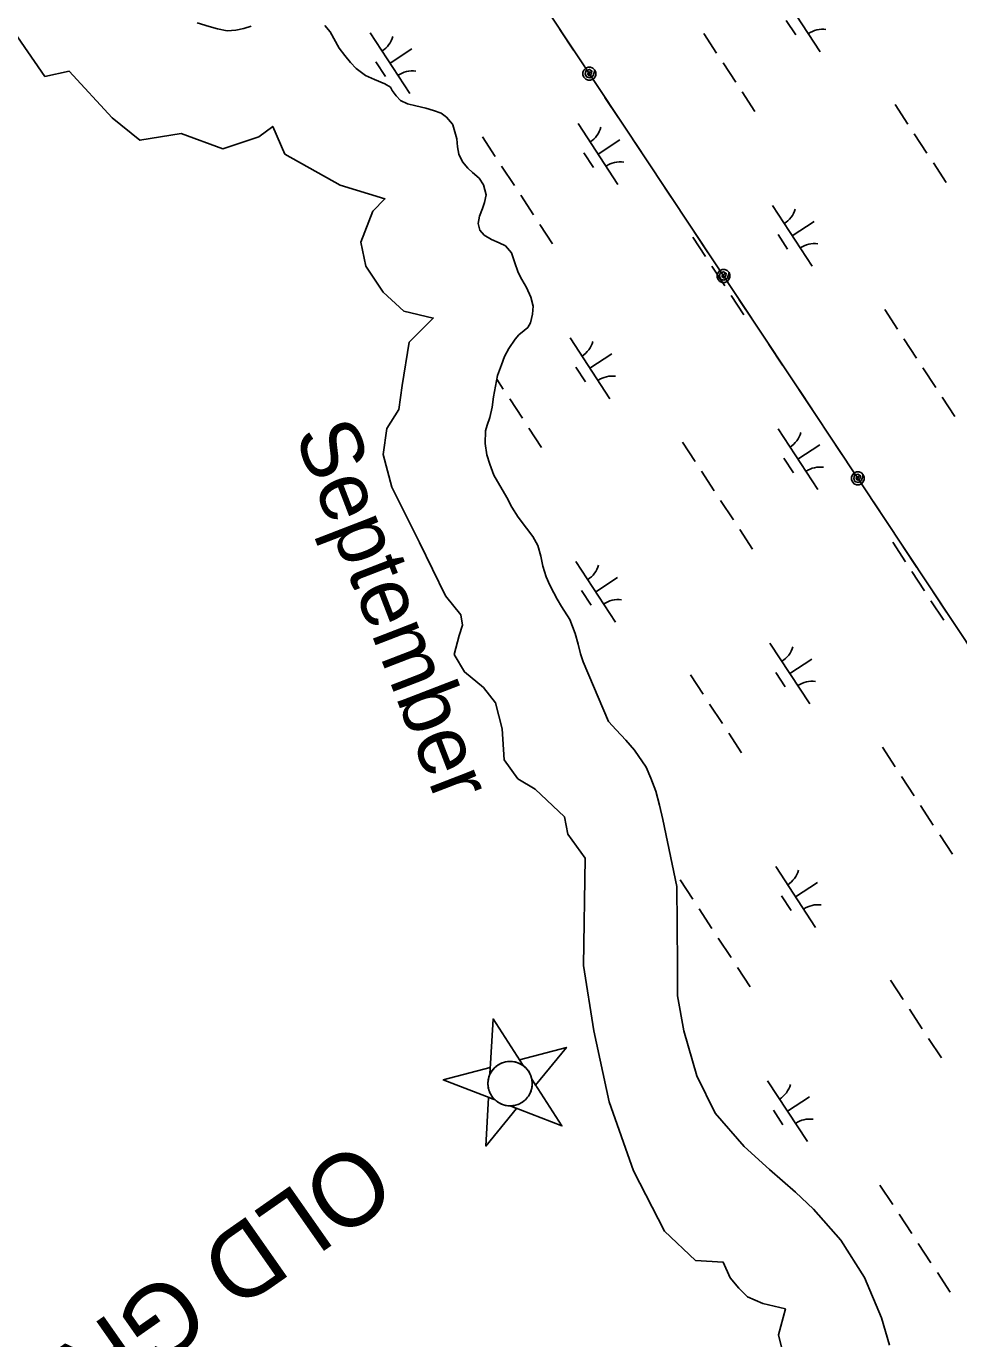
# Model space of a CAD drawing. Extents: x 3945642 to 3966284, y 206476 to 228921.
# Drawn here: x 3958060 to 3958701, y 215442 to 216345 of the extents above; entities that cross this region are included whole.
import ezdxf

# ---------------------------------------------------------------- set-up
doc = ezdxf.new("R2010")
doc.units = 0
for name, color, linetype in [('V-CHAN-NAID', 7, 'Continuous'), ('V-RIVR-EDGE', 7, 'Continuous'), ('V-RIVR-IDEN', 7, 'Continuous'), ('V-UTIL-LINE', 7, 'Continuous'), ('V-WETL-SWMP', 7, 'Continuous')]:
    doc.layers.add(name, color=color, linetype=linetype)

msp = doc.modelspace()

# ---------------------------------------------------------------- linework, layer by layer
at = {"layer": 'V-CHAN-NAID'}
for points in [[(3958401.45, 215629.91), (3958380.76, 215662.08), (3958378.6, 215623.89), (3958379.09, 215624.88), (3958379.55, 215625.66), (3958380.15, 215626.55), (3958380.82, 215627.4), (3958381.27, 215627.91), (3958381.86, 215628.51), (3958382.39, 215629.01), (3958383.01, 215629.52), (3958383.71, 215630.04), (3958384.37, 215630.48), (3958385.26, 215631), (3958385.99, 215631.37), (3958387.02, 215631.81), (3958387.96, 215632.13), (3958388.91, 215632.4), (3958389.79, 215632.58), (3958390.66, 215632.71), (3958391.52, 215632.79), (3958392.54, 215632.82), (3958393.44, 215632.79), (3958394.24, 215632.72), (3958394.99, 215632.62), (3958395.91, 215632.43), (3958396.6, 215632.26), (3958397.66, 215631.92), (3958398.35, 215631.65), (3958399.26, 215631.24), (3958400.13, 215630.77), (3958400.81, 215630.35)], [(3958401.45, 215629.91), (3958398.86, 215633.94), (3958431.21, 215642.47), (3958410.05, 215616.56), (3958407.46, 215620.59), (3958407.27, 215621.41), (3958406.95, 215622.45), (3958406.58, 215623.43), (3958406.15, 215624.37), (3958405.88, 215624.89), (3958405.5, 215625.55), (3958405.03, 215626.27), (3958404.62, 215626.83), (3958404.02, 215627.57), (3958403.55, 215628.08), (3958402.9, 215628.72), (3958402.31, 215629.25), (3958401.89, 215629.59)], [(3958382.17, 215606.3), (3958346.52, 215620.15), (3958378.87, 215628.68), (3958378.6, 215623.89), (3958378.37, 215623.36), (3958377.97, 215622.27), (3958377.71, 215621.38), (3958377.48, 215620.35), (3958377.34, 215619.43), (3958377.25, 215618.51), (3958377.22, 215617.65), (3958377.25, 215616.66), (3958377.33, 215615.7), (3958377.48, 215614.72), (3958377.65, 215613.97), (3958377.87, 215613.14), (3958378.24, 215612.06), (3958378.54, 215611.34), (3958378.99, 215610.42), (3958379.37, 215609.75), (3958379.87, 215608.96), (3958380.36, 215608.28), (3958380.9, 215607.61), (3958381.55, 215606.9)], [(3958407.46, 215620.59), (3958428.15, 215588.43), (3958392.5, 215602.28), (3958393.37, 215602.31), (3958394.42, 215602.4), (3958395.27, 215602.54), (3958396.29, 215602.76), (3958397.19, 215603.02), (3958397.99, 215603.3), (3958398.93, 215603.7), (3958399.63, 215604.06), (3958400.59, 215604.61), (3958401.45, 215605.18), (3958402.32, 215605.87), (3958402.99, 215606.46), (3958403.79, 215607.28), (3958404.51, 215608.13), (3958405.13, 215608.99), (3958405.56, 215609.65), (3958406.09, 215610.6), (3958406.52, 215611.51), (3958406.9, 215612.49), (3958407.2, 215613.44), (3958407.42, 215614.34), (3958407.61, 215615.45), (3958407.73, 215616.56), (3958407.76, 215617.59), (3958407.72, 215618.69), (3958407.63, 215619.51)], [(3958392.5, 215602.28), (3958396.97, 215600.54), (3958375.81, 215574.64), (3958377.7, 215608.03), (3958382.17, 215606.3), (3958382.82, 215605.73), (3958383.5, 215605.21), (3958384.47, 215604.56), (3958385.32, 215604.07), (3958386.29, 215603.6), (3958387.28, 215603.2), (3958388.22, 215602.89), (3958389.06, 215602.67), (3958390.04, 215602.48), (3958390.95, 215602.36), (3958391.87, 215602.29)]]:
    msp.add_lwpolyline(points, close=True, dxfattribs=at)
msp.add_circle((3958392.49, 215617.55), 15.27, dxfattribs=at)
at = {"layer": 'V-RIVR-EDGE'}
msp.add_lwpolyline([(3958053.53, 216337.62), (3958072.53, 216310.31), (3958089.15, 216313.88), (3958118.83, 216281.82), (3958137.82, 216266.39), (3958166.32, 216271.14), (3958194.81, 216260.45), (3958219.74, 216268.76), (3958229.24, 216275.89), (3958237.55, 216256.89), (3958275.54, 216235.52), (3958306.41, 216226.02), (3958298.1, 216217.71), (3958289.79, 216196.34), (3958293.35, 216179.72), (3958305.22, 216161.91), (3958319.47, 216148.85), (3958339.65, 216144.11), (3958323.03, 216127.48), (3958318.28, 216097.8), (3958315.9, 216081.18), (3958307.59, 216068.12), (3958305.22, 216050.32), (3958311.16, 216027.76), (3958330.15, 215989.77), (3958347.96, 215952.96), (3958358.64, 215939.9), (3958359.83, 215932.78), (3958357.46, 215925.66), (3958353.9, 215912.6), (3958361.02, 215900.73), (3958374.08, 215890.04), (3958382.39, 215879.36), (3958387.14, 215861.55), (3958388.32, 215840.18), (3958397.82, 215827.12), (3958409.69, 215820), (3958429.88, 215801), (3958432.25, 215789.13), (3958444.12, 215772.51), (3958442.94, 215698.9), (3958450.06, 215653.79), (3958460.74, 215605.11), (3958477.37, 215557.62), (3958498.74, 215516.07), (3958520.1, 215495.89), (3958539.1, 215494.7), (3958543.85, 215484.01), (3958549.79, 215476.89), (3958555.72, 215470.96), (3958566.41, 215466.21), (3958581.84, 215462.65), (3958577.09, 215444.84), (3958579.47, 215435.34)], dxfattribs=at)
at = {"layer": 'V-UTIL-LINE'}
for points in [[(3958881.28, 222827.27), (3957109.88, 218326.97), (3961480.16, 211741.64)], [(3958426.79, 216342.56), (3958436.19, 216328.39)], [(3958446.98, 216312.17), (3958447.51, 216313.51), (3958446.38, 216313.24), (3958445.9, 216311.96), (3958446.84, 216310.83), (3958448.3, 216311.7), (3958448.82, 216313.99), (3958447.01, 216315.11), (3958444.7, 216314.36), (3958444.13, 216312.14), (3958444.93, 216310.05), (3958447.24, 216309.35), (3958449.62, 216310.74), (3958450.73, 216314.66), (3958449.49, 216315.91), (3958447.87, 216316.58), (3958446.11, 216316.59), (3958444.49, 216315.92), (3958443.24, 216314.69), (3958442.57, 216313.07), (3958442.56, 216311.31), (3958443.23, 216309.69), (3958444.47, 216308.44), (3958446.09, 216307.76), (3958447.84, 216307.76), (3958449.47, 216308.42), (3958450.71, 216309.66), (3958451.39, 216311.28), (3958451.39, 216313.04), (3958450.73, 216314.66)], [(3958457.76, 216295.9), (3958467.16, 216281.73)], [(3958478.22, 216265.07), (3958487.62, 216250.91)], [(3958498.68, 216234.24), (3958508.08, 216220.08)], [(3958519.13, 216203.41), (3958528.53, 216189.25)], [(3958539.32, 216173.03), (3958539.85, 216174.36), (3958538.72, 216174.1), (3958538.24, 216172.81), (3958539.18, 216171.69), (3958540.64, 216172.56), (3958541.16, 216174.84), (3958539.35, 216175.97), (3958537.04, 216175.21), (3958536.47, 216172.99), (3958537.28, 216170.91), (3958539.58, 216170.21), (3958541.96, 216171.59), (3958543.07, 216175.52), (3958541.83, 216176.76), (3958540.21, 216177.44), (3958538.46, 216177.44), (3958536.83, 216176.78), (3958535.59, 216175.54), (3958534.91, 216173.92), (3958534.9, 216172.16), (3958535.57, 216170.54), (3958536.81, 216169.29), (3958538.43, 216168.62), (3958540.18, 216168.61), (3958541.81, 216169.28), (3958543.05, 216170.52), (3958543.73, 216172.14), (3958543.74, 216173.89), (3958543.07, 216175.52)], [(3958550.1, 216156.75), (3958559.5, 216142.59)], [(3958570.56, 216125.92), (3958579.96, 216111.76)], [(3958591.02, 216095.09), (3958600.42, 216080.93)], [(3958611.48, 216064.27), (3958620.88, 216050.1)], [(3958631.66, 216033.88), (3958632.2, 216035.22), (3958631.06, 216034.95), (3958630.59, 216033.66), (3958631.53, 216032.54), (3958632.99, 216033.41), (3958633.51, 216035.7), (3958631.69, 216036.82), (3958629.38, 216036.06), (3958628.82, 216033.85), (3958629.62, 216031.76), (3958631.93, 216031.06), (3958634.31, 216032.44), (3958635.41, 216036.37), (3958634.18, 216037.61), (3958632.55, 216038.29), (3958630.8, 216038.3), (3958629.17, 216037.63), (3958627.93, 216036.39), (3958627.25, 216034.77), (3958627.25, 216033.02), (3958627.91, 216031.39), (3958629.15, 216030.15), (3958630.77, 216029.47), (3958632.53, 216029.46), (3958634.15, 216030.13), (3958635.4, 216031.37), (3958636.07, 216032.99), (3958636.08, 216034.75), (3958635.41, 216036.37)], [(3958642.44, 216017.61), (3958651.84, 216003.44)], [(3958662.9, 215986.78), (3958672.3, 215972.61)], [(3958683.36, 215955.95), (3958692.76, 215941.78)]]:
    msp.add_lwpolyline(points, dxfattribs=at)
at = {"layer": 'V-WETL-SWMP'}
for p, q in [((3958578.43, 216369), (3958605.83, 216327.18)), ((3958177.24, 216347.25), (3958185.58, 216344.59)), ((3958185.58, 216344.59), (3958191.12, 216342.97)), ((3958209.35, 216343.34), (3958214.33, 216344.82)), ((3958265.07, 216345.4), (3958268.79, 216340.9)), ((3958582.39, 216348.88), (3958588.97, 216338.84)), ((3958191.12, 216342.97), (3958197.88, 216341.62)), ((3958197.88, 216341.62), (3958203.79, 216342.08)), ((3958203.79, 216342.08), (3958209.35, 216343.34)), ((3958268.79, 216340.9), (3958274.83, 216329.83)), ((3958296.22, 216340.39), (3958323.62, 216298.57)), ((3958525.79, 216339.8), (3958534.56, 216326.42)), ((3958274.83, 216329.83), (3958278.9, 216324.76)), ((3958309.92, 216319.48), (3958324.98, 216329.34)), ((3958278.9, 216324.76), (3958282.76, 216319.83)), ((3958282.76, 216319.83), (3958286.62, 216315.84)), ((3958300.18, 216320.27), (3958306.75, 216310.23)), ((3958538.94, 216319.73), (3958547.71, 216306.34)), ((3958286.62, 216315.84), (3958292.93, 216310.9)), ((3958292.93, 216310.9), (3958299.32, 216308.11)), ((3958299.32, 216308.11), (3958306.29, 216305.32)), ((3958306.29, 216305.32), (3958310.17, 216302.99)), ((3958310.17, 216302.99), (3958311.45, 216300.68)), ((3958311.45, 216300.68), (3958314.02, 216297.05)), ((3958552.09, 216299.65), (3958560.86, 216286.27)), ((3958314.02, 216297.05), (3958317.16, 216293.72)), ((3958317.16, 216293.72), (3958321.9, 216291.38)), ((3958321.9, 216291.38), (3958327.66, 216290.04)), ((3958327.66, 216290.04), (3958334.42, 216288.41)), ((3958657.33, 216290.94), (3958666.09, 216277.55)), ((3958334.42, 216288.41), (3958339.81, 216286.93)), ((3958339.81, 216286.93), (3958344.99, 216284.94)), ((3958344.99, 216284.94), (3958348.65, 216282.25)), ((3958348.65, 216282.25), (3958352.79, 216277.54)), ((3958352.79, 216277.54), (3958353.08, 216277.1)), ((3958353.08, 216277.1), (3958355.75, 216267.28)), ((3958439.29, 216277.85), (3958466.69, 216236.03)), ((3958355.75, 216267.28), (3958356.36, 216261.95)), ((3958373.5, 216268.73), (3958382.27, 216255.34)), ((3958452.99, 216256.94), (3958468.05, 216266.8)), ((3958670.48, 216270.86), (3958679.25, 216257.48)), ((3958356.36, 216261.95), (3958357.33, 216256.82)), ((3958357.33, 216256.82), (3958359.81, 216251.55)), ((3958443.25, 216257.73), (3958449.83, 216247.69)), ((3958359.81, 216251.55), (3958363.31, 216247.2)), ((3958363.31, 216247.2), (3958366.61, 216244.29)), ((3958366.61, 216244.29), (3958371.12, 216240.3)), ((3958386.65, 216248.65), (3958395.42, 216235.27)), ((3958683.63, 216250.79), (3958692.4, 216237.4)), ((3958371.12, 216240.3), (3958374.19, 216235.73)), ((3958374.19, 216235.73), (3958375.94, 216228.95)), ((3958375.94, 216228.95), (3958374.96, 216223.62)), ((3958399.8, 216228.57), (3958408.57, 216215.19)), ((3958373.49, 216219.38), (3958371.37, 216214.28)), ((3958374.96, 216223.62), (3958373.49, 216219.38)), ((3958572.88, 216221.62), (3958600.28, 216179.8)), ((3958371.37, 216214.28), (3958370.46, 216209.24)), ((3958370.46, 216209.24), (3958371.73, 216204.55)), ((3958412.96, 216208.5), (3958421.72, 216195.12)), ((3958586.58, 216200.71), (3958601.64, 216210.58)), ((3958371.73, 216204.55), (3958374.66, 216201.07)), ((3958374.66, 216201.07), (3958379.61, 216198.22)), ((3958518.19, 216199.79), (3958526.95, 216186.4)), ((3958576.84, 216201.5), (3958583.41, 216191.47)), ((3958379.61, 216198.22), (3958384.93, 216195.95)), ((3958384.93, 216195.95), (3958389.38, 216193.83)), ((3958389.38, 216193.83), (3958393.52, 216188.9)), ((3958393.52, 216188.9), (3958395.57, 216182.83)), ((3958395.57, 216182.83), (3958398.04, 216175.54)), ((3958398.04, 216175.54), (3958400.67, 216170.69)), ((3958531.34, 216179.71), (3958540.11, 216166.33)), ((3958400.67, 216170.69), (3958403.8, 216165.05)), ((3958403.8, 216165.05), (3958406.71, 216158.47)), ((3958406.71, 216158.47), (3958408.4, 216152.33)), ((3958544.49, 216159.64), (3958553.26, 216146.25)), ((3958408, 216146.78), (3958406.44, 216140.74)), ((3958408.4, 216152.33), (3958408, 216146.78)), ((3958650.16, 216149.96), (3958658.93, 216136.57)), ((3958404.62, 216137.73), (3958402.23, 216135.65)), ((3958406.44, 216140.74), (3958404.62, 216137.73)), ((3958396.06, 216129.65), (3958391.69, 216123.19)), ((3958398.6, 216132.51), (3958396.06, 216129.65)), ((3958402.23, 216135.65), (3958398.6, 216132.51)), ((3958433.74, 216130.47), (3958461.14, 216088.65)), ((3958663.31, 216129.88), (3958672.08, 216116.5)), ((3958391.69, 216123.19), (3958388.69, 216117.66)), ((3958447.44, 216109.56), (3958462.5, 216119.42)), ((3958386.49, 216111.91), (3958383.77, 216104.66)), ((3958388.69, 216117.66), (3958386.49, 216111.91)), ((3958437.7, 216110.35), (3958444.27, 216100.31)), ((3958676.46, 216109.81), (3958685.23, 216096.42)), ((3958383.77, 216104.66), (3958381, 216089.83)), ((3958383.3, 216102.14), (3958387.82, 216095.25)), ((3958380.09, 216082.77), (3958378.45, 216075.8)), ((3958381, 216089.83), (3958380.09, 216082.77)), ((3958392.2, 216088.56), (3958400.97, 216075.18)), ((3958689.61, 216089.73), (3958698.38, 216076.35)), ((3958378.45, 216075.8), (3958376.76, 216070.4)), ((3958375.65, 216066.45), (3958375.23, 216057.73)), ((3958376.76, 216070.4), (3958375.65, 216066.45)), ((3958405.35, 216068.48), (3958414.12, 216055.1)), ((3958576.81, 216067.93), (3958604.21, 216026.11)), ((3958375.23, 216057.73), (3958376.54, 216050.01)), ((3958511.02, 216058.81), (3958519.79, 216045.42)), ((3958590.51, 216047.02), (3958605.57, 216056.88)), ((3958376.54, 216050.01), (3958378.51, 216043.73)), ((3958580.77, 216047.81), (3958587.35, 216037.77)), ((3958378.51, 216043.73), (3958381.41, 216036.07)), ((3958524.17, 216038.73), (3958532.94, 216025.35)), ((3958381.41, 216036.07), (3958390.31, 216020.58)), ((3958390.31, 216020.58), (3958393.79, 216014.07)), ((3958537.32, 216018.66), (3958546.09, 216005.27)), ((3958393.79, 216014.07), (3958397.93, 216007.2)), ((3958397.93, 216007.2), (3958403.78, 215999.52)), ((3958403.78, 215999.52), (3958408.21, 215993.86)), ((3958408.21, 215993.86), (3958411.48, 215987.57)), ((3958550.48, 215998.58), (3958559.24, 215985.2)), ((3958411.48, 215987.57), (3958413.59, 215980.35)), ((3958655.71, 215989.87), (3958664.48, 215976.48)), ((3958413.59, 215980.35), (3958415.05, 215973.42)), ((3958415.05, 215973.42), (3958417.38, 215966.06)), ((3958437.68, 215976.78), (3958465.07, 215934.96)), ((3958417.38, 215966.06), (3958419.93, 215960.42)), ((3958451.38, 215955.87), (3958466.43, 215965.73)), ((3958668.86, 215969.79), (3958677.63, 215956.41)), ((3958419.93, 215960.42), (3958422.56, 215955.07)), ((3958441.63, 215956.66), (3958448.21, 215946.62)), ((3958422.56, 215955.07), (3958424.83, 215950.65)), ((3958424.83, 215950.65), (3958427.9, 215945.66)), ((3958682.01, 215949.72), (3958690.78, 215936.33)), ((3958427.9, 215945.66), (3958433.63, 215936.69)), ((3958433.63, 215936.69), (3958437.18, 215927.25)), ((3958437.18, 215927.25), (3958439.3, 215919.88)), ((3958439.3, 215919.88), (3958440.94, 215913.23)), ((3958571.26, 215920.55), (3958598.66, 215878.73)), ((3958440.94, 215913.23), (3958442.83, 215907.55)), ((3958442.83, 215907.55), (3958460.28, 215866.66)), ((3958584.96, 215899.64), (3958600.02, 215909.51)), ((3958516.57, 215898.72), (3958525.34, 215885.33)), ((3958575.22, 215900.43), (3958581.79, 215890.39)), ((3958529.72, 215878.64), (3958538.49, 215865.26)), ((3958460.28, 215866.66), (3958465.43, 215860.95)), ((3958465.43, 215860.95), (3958472.02, 215853.78)), ((3958542.87, 215858.56), (3958551.64, 215845.18)), ((3958472.02, 215853.78), (3958478, 215846.86)), ((3958648.54, 215848.89), (3958657.31, 215835.5)), ((3958478, 215846.86), (3958486, 215835.22)), ((3958486, 215835.22), (3958489.33, 215827.72)), ((3958489.33, 215827.72), (3958492.76, 215818.65)), ((3958661.69, 215828.81), (3958670.46, 215815.43)), ((3958492.76, 215818.65), (3958495.23, 215809.1)), ((3958495.23, 215809.1), (3958497.57, 215799.18)), ((3958674.84, 215808.74), (3958683.61, 215795.35)), ((3958497.57, 215799.18), (3958507.26, 215753.13)), ((3958688, 215788.66), (3958696.76, 215775.28)), ((3958575.2, 215766.86), (3958602.6, 215725.04)), ((3958509.4, 215757.74), (3958518.17, 215744.35)), ((3958507.26, 215753.13), (3958507.51, 215727.11)), ((3958588.9, 215745.95), (3958603.95, 215755.81)), ((3958579.15, 215746.74), (3958585.73, 215736.7)), ((3958522.55, 215737.66), (3958531.32, 215724.28)), ((3958507.51, 215727.11), (3958507.74, 215698.68)), ((3958535.71, 215717.59), (3958544.47, 215704.2)), ((3958507.74, 215698.68), (3958507.62, 215677.86)), ((3958548.86, 215697.51), (3958557.63, 215684.13)), ((3958654.09, 215688.8), (3958662.86, 215675.41)), ((3958507.62, 215677.86), (3958511.88, 215653.81)), ((3958667.24, 215668.72), (3958676.01, 215655.34)), ((3958511.88, 215653.81), (3958520.9, 215622.93)), ((3958680.39, 215648.65), (3958689.16, 215635.26)), ((3958520.9, 215622.93), (3958533.56, 215597.23)), ((3958569.64, 215619.48), (3958597.04, 215577.66)), ((3958583.34, 215598.57), (3958598.4, 215608.44)), ((3958533.56, 215597.23), (3958553.44, 215574.29)), ((3958573.6, 215599.36), (3958580.18, 215589.32)), ((3958553.44, 215574.29), (3958570.97, 215558.57)), ((3958570.97, 215558.57), (3958588.89, 215542.85)), ((3958588.89, 215542.85), (3958601.23, 215531.17)), ((3958646.92, 215547.82), (3958655.69, 215534.43)), ((3958601.23, 215531.17), (3958619.92, 215509.84)), ((3958660.07, 215527.74), (3958668.84, 215514.36)), ((3958619.92, 215509.84), (3958636.19, 215484.12)), ((3958673.23, 215507.67), (3958681.99, 215494.28)), ((3958686.38, 215487.59), (3958695.15, 215474.21)), ((3958636.19, 215484.12), (3958648.03, 215456.42)), ((3958648.03, 215456.42), (3958653.53, 215437.57))]:
    msp.add_line(p, q, dxfattribs=at)
for centre, start, end in [((3958294.98, 216342.71), 302.45745, 344.00111), ((3958607.47, 216325.11), 82.45745, 124.00111), ((3958325.25, 216296.51), 82.45745, 124.00111), ((3958438.06, 216280.17), 302.45745, 344.00111), ((3958468.33, 216233.96), 82.45745, 124.00111), ((3958571.64, 216223.95), 302.45745, 344.00111), ((3958601.91, 216177.74), 82.45745, 124.00111), ((3958432.5, 216132.8), 302.45745, 344.00111), ((3958462.78, 216086.59), 82.45745, 124.00111), ((3958575.58, 216070.25), 302.45745, 344.00111), ((3958605.85, 216024.04), 82.45745, 124.00111), ((3958436.44, 215979.1), 302.45745, 344.00111), ((3958466.71, 215932.89), 82.45745, 124.00111), ((3958570.02, 215922.88), 302.45745, 344.00111), ((3958600.3, 215876.67), 82.45745, 124.00111), ((3958573.96, 215769.18), 302.45745, 344.00111), ((3958604.23, 215722.97), 82.45745, 124.00111), ((3958568.4, 215621.81), 302.45745, 344.00111), ((3958598.68, 215575.6), 82.45745, 124.00111)]:
    msp.add_arc(centre, 17.62, start, end, dxfattribs=at)

# ---------------------------------------------------------------- texts
at = {"layer": 'V-CHAN-NAID'}
msp.add_text('OLD GRAND BAYOU "10"', height=50, rotation=214.98728, dxfattribs=at).set_placement((3958287.98, 215580))
at = {"layer": 'V-RIVR-IDEN'}
msp.add_text('September', height=42, rotation=291.10933, dxfattribs=at).set_placement((3958243.91, 216064.24))

doc.saveas('drawing.dxf')
